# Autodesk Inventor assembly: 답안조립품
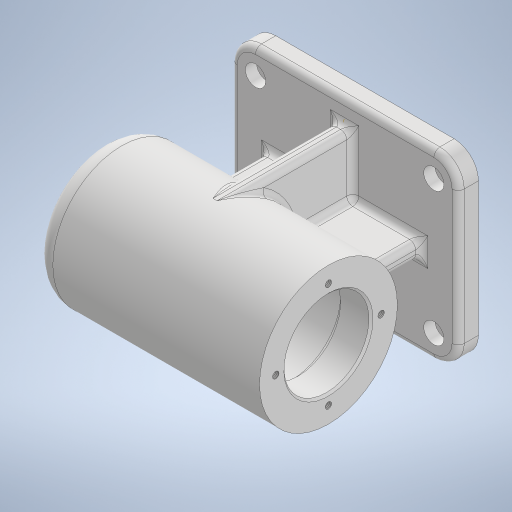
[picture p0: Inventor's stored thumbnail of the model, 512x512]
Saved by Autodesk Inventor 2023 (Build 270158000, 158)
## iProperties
Created: 2026-08
Part Number: 답안조립품
Document SubType Name: Assembly
Designer: home
Author: home
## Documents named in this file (2)
- C:\Users\kimgi\Desktop\760803V1006\답안조립품.iam
- C:\Users\kimgi\Desktop\760803V1006\본체.ipt
